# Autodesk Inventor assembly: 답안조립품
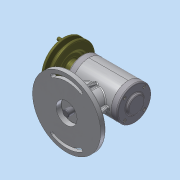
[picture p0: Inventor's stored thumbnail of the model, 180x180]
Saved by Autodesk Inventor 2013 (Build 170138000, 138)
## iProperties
Created: 2017-06
Part Number: 답안조립품
Document SubType Name: Assembly
Designer: Administrator
Author: Administrator
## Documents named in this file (15)
- C:\Users\Administrator\Desktop\370608V1023\답안조립품.iam
- C:\Users\Administrator\Desktop\370608V1023\V-벨트풀리.ipt
- C:\Users\Administrator\Desktop\370608V1023\뒤커버.ipt
- C:\Users\Administrator\Desktop\370608V1023\멈춤나사 M3x8.ipt
- C:\Users\Administrator\Desktop\370608V1023\베어링 6201.ipt
- C:\Users\Administrator\Desktop\370608V1023\베어링 6202.ipt
- C:\Users\Administrator\Desktop\370608V1023\본체.ipt
- C:\Users\Administrator\Desktop\370608V1023\본체커버.ipt
- C:\Users\Administrator\Desktop\370608V1023\볼트 M3x0.5x8.ipt
- C:\Users\Administrator\Desktop\370608V1023\슬라이드.ipt
- C:\Users\Administrator\Desktop\370608V1023\앞커버.ipt
- C:\Users\Administrator\Desktop\370608V1023\오일실 12 22 7.ipt
- C:\Users\Administrator\Desktop\370608V1023\키 4 x 4 x 18.ipt
- C:\Users\Administrator\Desktop\370608V1023\편심축.ipt
- C:\Users\Administrator\Desktop\370608V1023\스프링-[가변].ipt
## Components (1 placed, 1 different names)
1. V-벨트풀리:1
